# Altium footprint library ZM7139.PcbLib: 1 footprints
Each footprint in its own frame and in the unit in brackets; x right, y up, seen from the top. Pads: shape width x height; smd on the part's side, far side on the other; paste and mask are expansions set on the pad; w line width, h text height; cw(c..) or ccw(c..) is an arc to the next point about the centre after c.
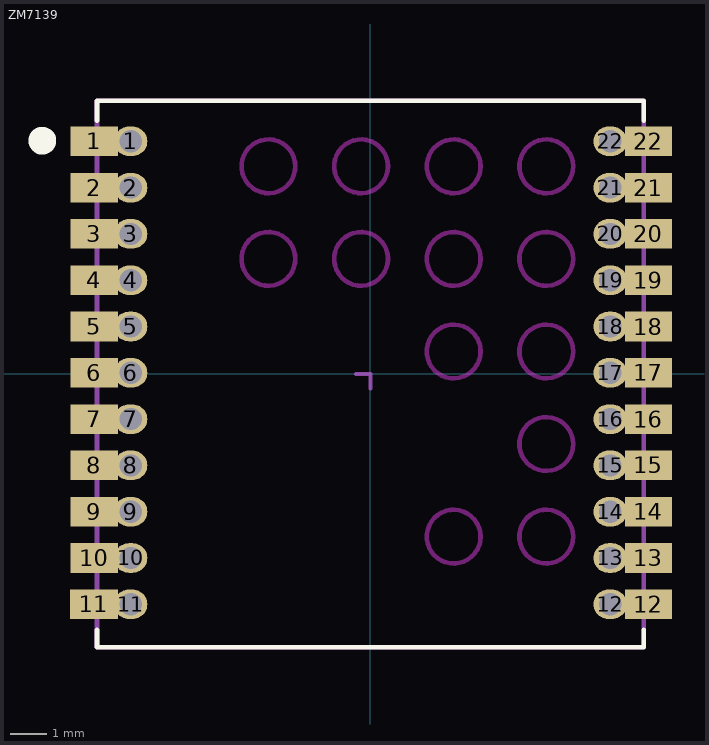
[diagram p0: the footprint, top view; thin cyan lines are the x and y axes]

## ZM7139 [mil]
pads (44):
  rect 51.18x32 smd paste-19.68: 1(-298.29,251.28) 2(-298.29,201.28) 3(-298.29,151.28) 4(-298.29,101.28) 5(-298.29,51.28) 6(-298.29,1.28) 7(-298.29,-48.72) 8(-298.29,-98.72) 9(-298.29,-148.72) 10(-298.29,-198.72) 12(300.28,-248.72) 13(300.28,-198.72) 14(300.28,-148.72) 15(300.28,-98.72) 16(300.28,-48.72) 17(300.28,1.28) 18(300.28,51.28) 19(300.28,101.28) 20(300.28,151.28) 21(300.28,201.28) 22(300.28,251.28)
  oval 36x32 hole 24: 1(-258.94,251.28) 2(-258.94,201.28) 3(-258.94,151.28) 4(-258.94,101.28) 5(-258.94,51.28) 6(-258.94,1.28) 7(-258.94,-48.72) 8(-258.94,-98.72) 9(-258.94,-148.72) 10(-258.94,-198.72) 11(-258.94,-248.72) 12(258.94,-248.72) 13(258.94,-198.72) 14(258.94,-148.72) 15(258.94,-98.72) 16(258.94,-48.72) 17(258.94,1.28) 18(258.94,51.28) 19(258.94,101.28) 20(258.94,151.28) 21(258.94,201.28) 22(258.94,251.28)
  rect 52x32 smd paste-19.68: 11(-298.7,-248.72)
Top Layer keep-out:
  circle w5: c189.84,-175.66 r29.05
  circle w5: c89.84,-175.66 r29.05
  circle w5: c189.84,-75.66 r29.05
  circle w5: c189.84,24.34 r29.05
  circle w5: c89.84,24.34 r29.05
  circle w5: c189.84,124.34 r29.05
  circle w5: c89.84,124.34 r29.05
  circle w5: c-10.16,124.34 r29.05
  circle w5: c-110.16,124.34 r29.05
  circle w5: c-110.16,224.34 r29.05
  circle w5: c-10.16,224.34 r29.05
  circle w5: c89.84,224.34 r29.05
  circle w5: c189.84,224.34 r29.05
Top Overlay:
  circle w15.75: c-354.33,251.97 r7.09
  lines w5: -295.28,-295.28 295.28,-295.28 -295.27,-295.28 -295.27,-276.16 ; 295.27,-295.28 295.27,-276.16 ; 295.27,-295.27 295.28,-276.16 ; 295.27,295.27 -295.28,295.27 -295.28,273.34 -295.28,295.28 295.27,295.28 ; 295.27,295.28 295.27,273.34 295.27,295.28
Mechanical 15:
  lines w4.5: -15.75,0 0,0 0,-15.75
  lines w5: -295.28,-295.28 295.27,-295.28 ; -295.28,-295.28 -295.28,295.27 -295.28,295.28 ; -295.28,-295.28 295.27,-295.28 ; -295.28,295.28 -294.28,295.28 ; -295.28,295.28 295.27,295.28 ; -294.28,295.28 -294.28,295.28 ; -294.28,295.28 295.27,295.28 ; 295.27,-295.28 295.27,295.28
